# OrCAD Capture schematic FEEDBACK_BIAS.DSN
size A
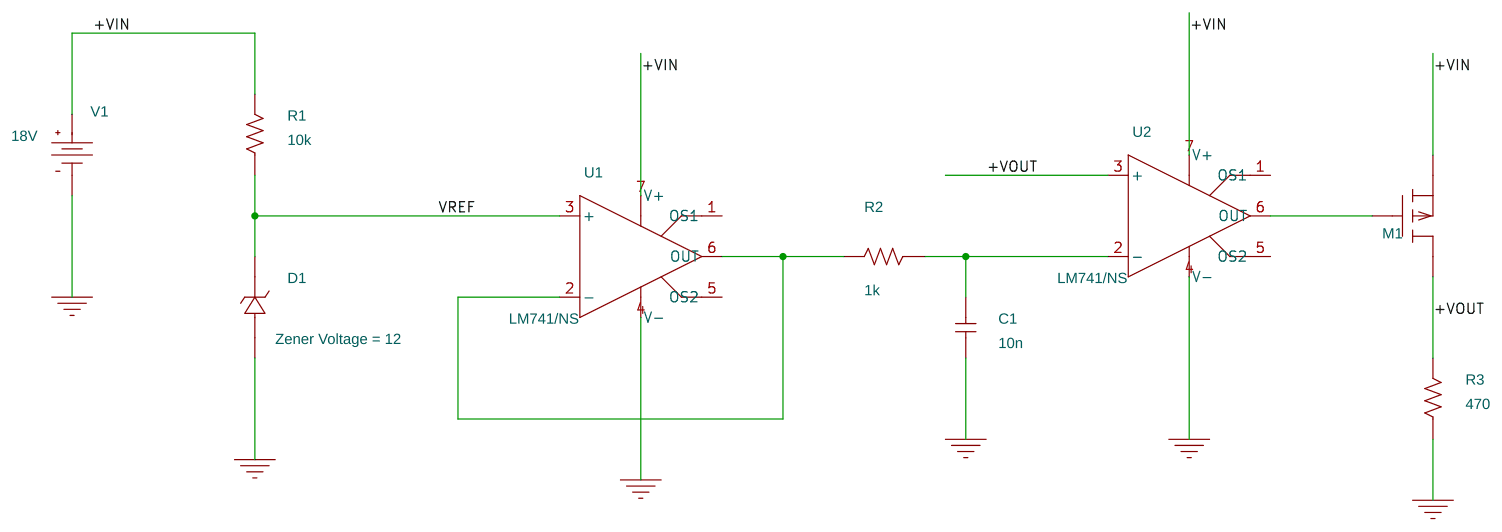
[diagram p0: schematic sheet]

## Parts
C1  10n  [cap196]
D1  ZENER
M1  POWER_PMOS_P
R1  10k  [AXRC05]
R2  1k  [AXRC05]
R3  470  [AXRC05]
U1  LM741/NS  [DIP1008W300L450]
U2  LM741/NS  [DIP1008W300L450]
V1  VDC

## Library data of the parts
C1 = C
D1 = zener: AppProp: mN=Zener12V,zV=12,TCBV=1.7,TCU=radio0; PartNumber: Zener12V; TCBV: 1.7; VZT: 12; Zener Voltage: 12
M1 = POWER_PMOS_P: BVDSS: -60; CISS: 3500p; COSS: 390p; CRSS: 290p; GFS: 20; IDSS: 1u; QG: 115n; RDSON: 19.5m; RG: 5.2; TRR: 45n; VGS_TH: -3; VSD: -1; V_QG: -10
R1-R3 = R
U1 U2 = LM741_NS
V1 = VDC: DC: 18V

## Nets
+VIN: M1.1(s) R1.2 U1.7(V+) U2.7(V+) V1.0(+)
0: C1.1 D1.1(AN) R3.1 U1.4(V-) U2.4(V-) V1.1(-)
+VOUT: M1.2(d) R3.2 U2.3(+)
VREF: D1.2(CAT) R1.1 U1.3(+)
N00307: R2.2 U1.2(-) U1.6(OUT)
N00471: C1.2 R2.1 U2.2(-)
N00896: M1.0(g) U2.6(OUT)

Not connected (* = marked no-connect by the designer): U1 1(OS1) 5(OS2); U2 1(OS1) 5(OS2)
